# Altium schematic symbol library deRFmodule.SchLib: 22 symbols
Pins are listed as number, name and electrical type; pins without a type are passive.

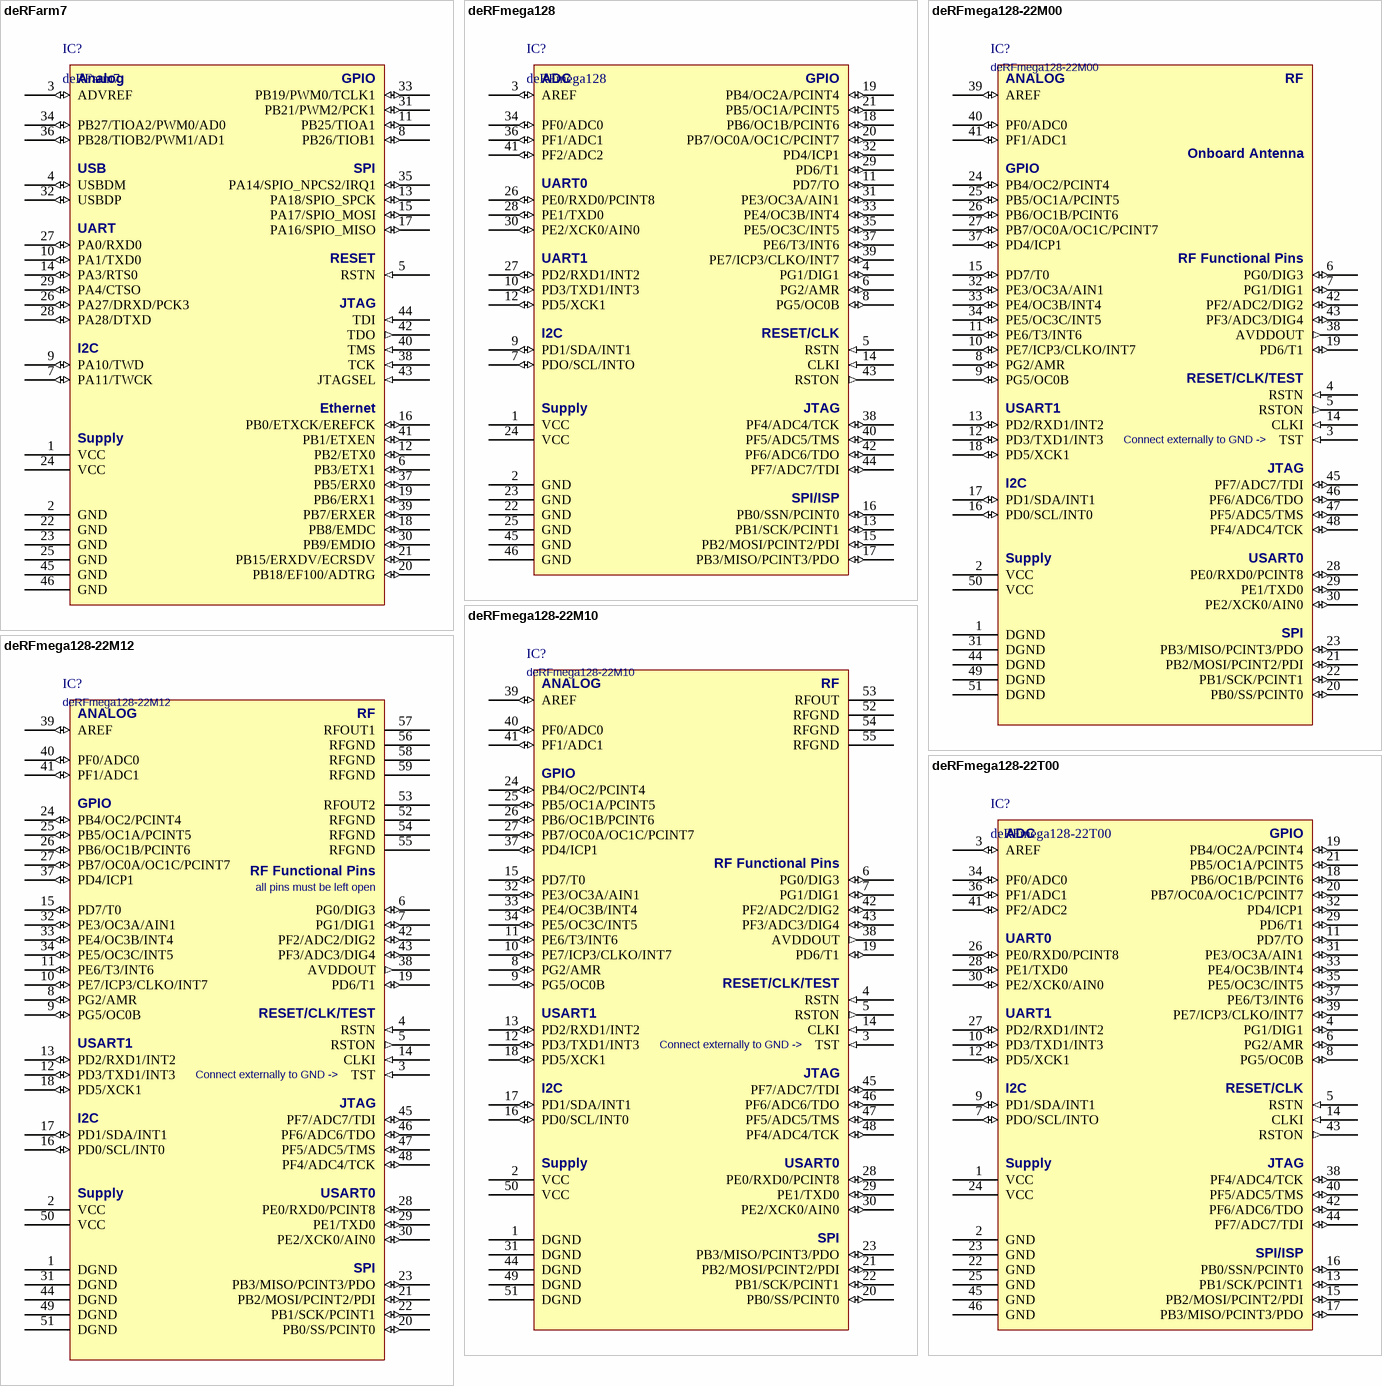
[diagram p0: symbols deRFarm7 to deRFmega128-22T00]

## deRFarm7
designator IC?
IEEE802.15.4 2.4GHz ARM7 based radio module
footprint deRFmodule_THT
footprint deRFmodule_SMT
pins: 1 VCC (power), 2 GND (power), 3 ADVREF (io), 4 USBDM (io), 5 RSTN (in), 6 PB3/ETX1 (io), 7 PA11/TWCK (io), 8 PB26/TIOB1 (io), 9 PA10/TWD (io), 10 PA1/TXD0 (io), 11 PB25/TIOA1 (io), 12 PB2/ETX0 (io), 13 PA18/SPIO_SPCK (io), 14 PA3/RTS0 (io), 15 PA17/SPIO_MOSI (io), 16 PB0/ETXCK/EREFCK (io), 17 PA16/SPIO_MISO (io), 18 PB8/EMDC (io), 19 PB6/ERX1 (io), 20 PB18/EF100/ADTRG (io), 21 PB15/ERXDV/ECRSDV (io), 22 GND (power), 23 GND (power), 24 VCC (power), 25 GND (power), 26 PA27/DRXD/PCK3 (io), 27 PA0/RXD0 (io), 28 PA28/DTXD (io), 29 PA4/CTSO (io), 30 PB9/EMDIO (io), 31 PB21/PWM2/PCK1 (io), 32 USBDP (io), 33 PB19/PWM0/TCLK1 (io), 34 PB27/TIOA2/PWM0/AD0 (io), 35 PA14/SPIO_NPCS2/IRQ1 (io), 36 PB28/TIOB2/PWM1/AD1 (io), 37 PB5/ERX0 (io), 38 TCK (in), 39 PB7/ERXER (io), 40 TMS (in), 41 PB1/ETXEN (io), 42 TDO (out), 43 JTAGSEL (in), 44 TDI (in), 45 GND (power), 46 GND (power)

## deRFmega128
designator IC?
IEEE802.15.4 2.4GHz AVR based radio module
footprint deRFmodule_THT
footprint deRFmodule_SMT
pins: 1 VCC (power), 2 GND (power), 3 AREF (io), 4 PG1/DIG1 (io), 5 RSTN (in), 6 PG2/AMR (io), 7 PDO/SCL/INTO (io), 8 PG5/OC0B (io), 9 PD1/SDA/INT1 (io), 10 PD3/TXD1/INT3 (io), 11 PD7/TO (io), 12 PD5/XCK1 (io), 13 PB1/SCK/PCINT1 (io), 14 CLKI (in), 15 PB2/MOSI/PCINT2/PDI (io), 16 PB0/SSN/PCINT0 (io), 17 PB3/MISO/PCINT3/PDO (io), 18 PB6/OC1B/PCINT6 (io), 19 PB4/OC2A/PCINT4 (io), 20 PB7/OC0A/OC1C/PCINT7 (io), 21 PB5/OC1A/PCINT5 (io), 22 GND (power), 23 GND (power), 24 VCC (power), 25 GND (power), 26 PE0/RXD0/PCINT8 (io), 27 PD2/RXD1/INT2 (io), 28 PE1/TXD0 (io), 29 PD6/T1 (io), 30 PE2/XCK0/AIN0 (io), 31 PE3/OC3A/AIN1 (io), 32 PD4/ICP1 (io), 33 PE4/OC3B/INT4 (io), 34 PF0/ADC0 (io), 35 PE5/OC3C/INT5 (io), 36 PF1/ADC1 (io), 37 PE6/T3/INT6 (io), 38 PF4/ADC4/TCK (io), 39 PE7/ICP3/CLKO/INT7 (io), 40 PF5/ADC5/TMS (io), 41 PF2/ADC2 (io), 42 PF6/ADC6/TDO (io), 43 RSTON (out), 44 PF7/ADC7/TDI (io), 45 GND (power), 46 GND (power)

## deRFmega128-22M00
designator IC?
IEEE802.15.4 2.4GHz AVR based radio module
footprint A-M00 (Footprint deRFmega128-22M00)
pins: 1 DGND (power), 2 VCC (power), 3 TST (in), 4 RSTN (in), 5 RSTON (out), 6 PG0/DIG3 (io), 7 PG1/DIG1 (io), 8 PG2/AMR (io), 9 PG5/OC0B (io), 10 PE7/ICP3/CLKO/INT7 (io), 11 PE6/T3/INT6 (io), 12 PD3/TXD1/INT3 (io), 13 PD2/RXD1/INT2 (io), 14 CLKI (in), 15 PD7/T0 (io), 16 PD0/SCL/INT0 (io), 17 PD1/SDA/INT1 (io), 18 PD5/XCK1 (io), 19 PD6/T1 (io), 20 PB0/SS/PCINT0 (io), 21 PB2/MOSI/PCINT2/PDI (io), 22 PB1/SCK/PCINT1 (io), 23 PB3/MISO/PCINT3/PDO (io), 24 PB4/OC2/PCINT4 (io), 25 PB5/OC1A/PCINT5 (io), 26 PB6/OC1B/PCINT6 (io), 27 PB7/OC0A/OC1C/PCINT7 (io), 28 PE0/RXD0/PCINT8 (io), 29 PE1/TXD0 (io), 30 PE2/XCK0/AIN0 (io), 31 DGND (power), 32 PE3/OC3A/AIN1 (io), 33 PE4/OC3B/INT4 (io), 34 PE5/OC3C/INT5 (io), 35 NC hidden, 36 NC hidden, 37 PD4/ICP1 (io), 38 AVDDOUT (out), 39 AREF (io), 40 PF0/ADC0 (io), 41 PF1/ADC1 (io), 42 PF2/ADC2/DIG2 (io), 43 PF3/ADC3/DIG4 (io), 44 DGND (power), 45 PF7/ADC7/TDI (io), 46 PF6/ADC6/TDO (io), 47 PF5/ADC5/TMS (io), 48 PF4/ADC4/TCK (io), 49 DGND (power), 50 VCC (power), 51 DGND (power)

## deRFmega128-22M10
designator IC?
IEEE802.15.4 2.4GHz AVR based radio module
footprint A-M10 (Footprint deRFmega128-22M10)
pins: 1 DGND (power), 2 VCC (power), 3 TST (in), 4 RSTN (in), 5 RSTON (out), 6 PG0/DIG3 (io), 7 PG1/DIG1 (io), 8 PG2/AMR (io), 9 PG5/OC0B (io), 10 PE7/ICP3/CLKO/INT7 (io), 11 PE6/T3/INT6 (io), 12 PD3/TXD1/INT3 (io), 13 PD2/RXD1/INT2 (io), 14 CLKI (in), 15 PD7/T0 (io), 16 PD0/SCL/INT0 (io), 17 PD1/SDA/INT1 (io), 18 PD5/XCK1 (io), 19 PD6/T1 (io), 20 PB0/SS/PCINT0 (io), 21 PB2/MOSI/PCINT2/PDI (io), 22 PB1/SCK/PCINT1 (io), 23 PB3/MISO/PCINT3/PDO (io), 24 PB4/OC2/PCINT4 (io), 25 PB5/OC1A/PCINT5 (io), 26 PB6/OC1B/PCINT6 (io), 27 PB7/OC0A/OC1C/PCINT7 (io), 28 PE0/RXD0/PCINT8 (io), 29 PE1/TXD0 (io), 30 PE2/XCK0/AIN0 (io), 31 DGND (power), 32 PE3/OC3A/AIN1 (io), 33 PE4/OC3B/INT4 (io), 34 PE5/OC3C/INT5 (io), 35 NC hidden, 36 NC hidden, 37 PD4/ICP1 (io), 38 AVDDOUT (out), 39 AREF (io), 40 PF0/ADC0 (io), 41 PF1/ADC1 (io), 42 PF2/ADC2/DIG2 (io), 43 PF3/ADC3/DIG4 (io), 44 DGND (power), 45 PF7/ADC7/TDI (io), 46 PF6/ADC6/TDO (io), 47 PF5/ADC5/TMS (io), 48 PF4/ADC4/TCK (io), 49 DGND (power), 50 VCC (power), 51 DGND (power), 52 RFGND (power), 53 RFOUT, 54 RFGND (power), 55 RFGND (power)

## deRFmega128-22M12
designator IC?
IEEE802.15.4 2.4GHz AVR based radio module + PA + Ant. Diversity
footprint A-M12 (Footprint deRFmega128-22M12)
pins: 1 DGND (power), 2 VCC (power), 3 TST (in), 4 RSTN (in), 5 RSTON (out), 6 PG0/DIG3 (io), 7 PG1/DIG1 (io), 8 PG2/AMR (io), 9 PG5/OC0B (io), 10 PE7/ICP3/CLKO/INT7 (io), 11 PE6/T3/INT6 (io), 12 PD3/TXD1/INT3 (io), 13 PD2/RXD1/INT2 (io), 14 CLKI (in), 15 PD7/T0 (io), 16 PD0/SCL/INT0 (io), 17 PD1/SDA/INT1 (io), 18 PD5/XCK1 (io), 19 PD6/T1 (io), 20 PB0/SS/PCINT0 (io), 21 PB2/MOSI/PCINT2/PDI (io), 22 PB1/SCK/PCINT1 (io), 23 PB3/MISO/PCINT3/PDO (io), 24 PB4/OC2/PCINT4 (io), 25 PB5/OC1A/PCINT5 (io), 26 PB6/OC1B/PCINT6 (io), 27 PB7/OC0A/OC1C/PCINT7 (io), 28 PE0/RXD0/PCINT8 (io), 29 PE1/TXD0 (io), 30 PE2/XCK0/AIN0 (io), 31 DGND (power), 32 PE3/OC3A/AIN1 (io), 33 PE4/OC3B/INT4 (io), 34 PE5/OC3C/INT5 (io), 35 NC hidden, 36 NC hidden, 37 PD4/ICP1 (io), 38 AVDDOUT (out), 39 AREF (io), 40 PF0/ADC0 (io), 41 PF1/ADC1 (io), 42 PF2/ADC2/DIG2 (io), 43 PF3/ADC3/DIG4 (io), 44 DGND (power), 45 PF7/ADC7/TDI (io), 46 PF6/ADC6/TDO (io), 47 PF5/ADC5/TMS (io), 48 PF4/ADC4/TCK (io), 49 DGND (power), 50 VCC (power), 51 DGND (power), 52 RFGND (power), 53 RFOUT2, 54 RFGND (power), 55 RFGND (power), 56 RFGND (power), 57 RFOUT1, 58 RFGND (power), 59 RFGND (power)

## deRFmega128-22T00
designator IC?
IEEE802.15.4 2.4GHz AVR based radio module
footprint deRFmodule_THT
pins: 1 VCC (power), 2 GND (power), 3 AREF (io), 4 PG1/DIG1 (io), 5 RSTN (in), 6 PG2/AMR (io), 7 PDO/SCL/INTO (io), 8 PG5/OC0B (io), 9 PD1/SDA/INT1 (io), 10 PD3/TXD1/INT3 (io), 11 PD7/TO (io), 12 PD5/XCK1 (io), 13 PB1/SCK/PCINT1 (io), 14 CLKI (in), 15 PB2/MOSI/PCINT2/PDI (io), 16 PB0/SSN/PCINT0 (io), 17 PB3/MISO/PCINT3/PDO (io), 18 PB6/OC1B/PCINT6 (io), 19 PB4/OC2A/PCINT4 (io), 20 PB7/OC0A/OC1C/PCINT7 (io), 21 PB5/OC1A/PCINT5 (io), 22 GND (power), 23 GND (power), 24 VCC (power), 25 GND (power), 26 PE0/RXD0/PCINT8 (io), 27 PD2/RXD1/INT2 (io), 28 PE1/TXD0 (io), 29 PD6/T1 (io), 30 PE2/XCK0/AIN0 (io), 31 PE3/OC3A/AIN1 (io), 32 PD4/ICP1 (io), 33 PE4/OC3B/INT4 (io), 34 PF0/ADC0 (io), 35 PE5/OC3C/INT5 (io), 36 PF1/ADC1 (io), 37 PE6/T3/INT6 (io), 38 PF4/ADC4/TCK (io), 39 PE7/ICP3/CLKO/INT7 (io), 40 PF5/ADC5/TMS (io), 41 PF2/ADC2 (io), 42 PF6/ADC6/TDO (io), 43 RSTON (out), 44 PF7/ADC7/TDI (io), 45 GND (power), 46 GND (power)

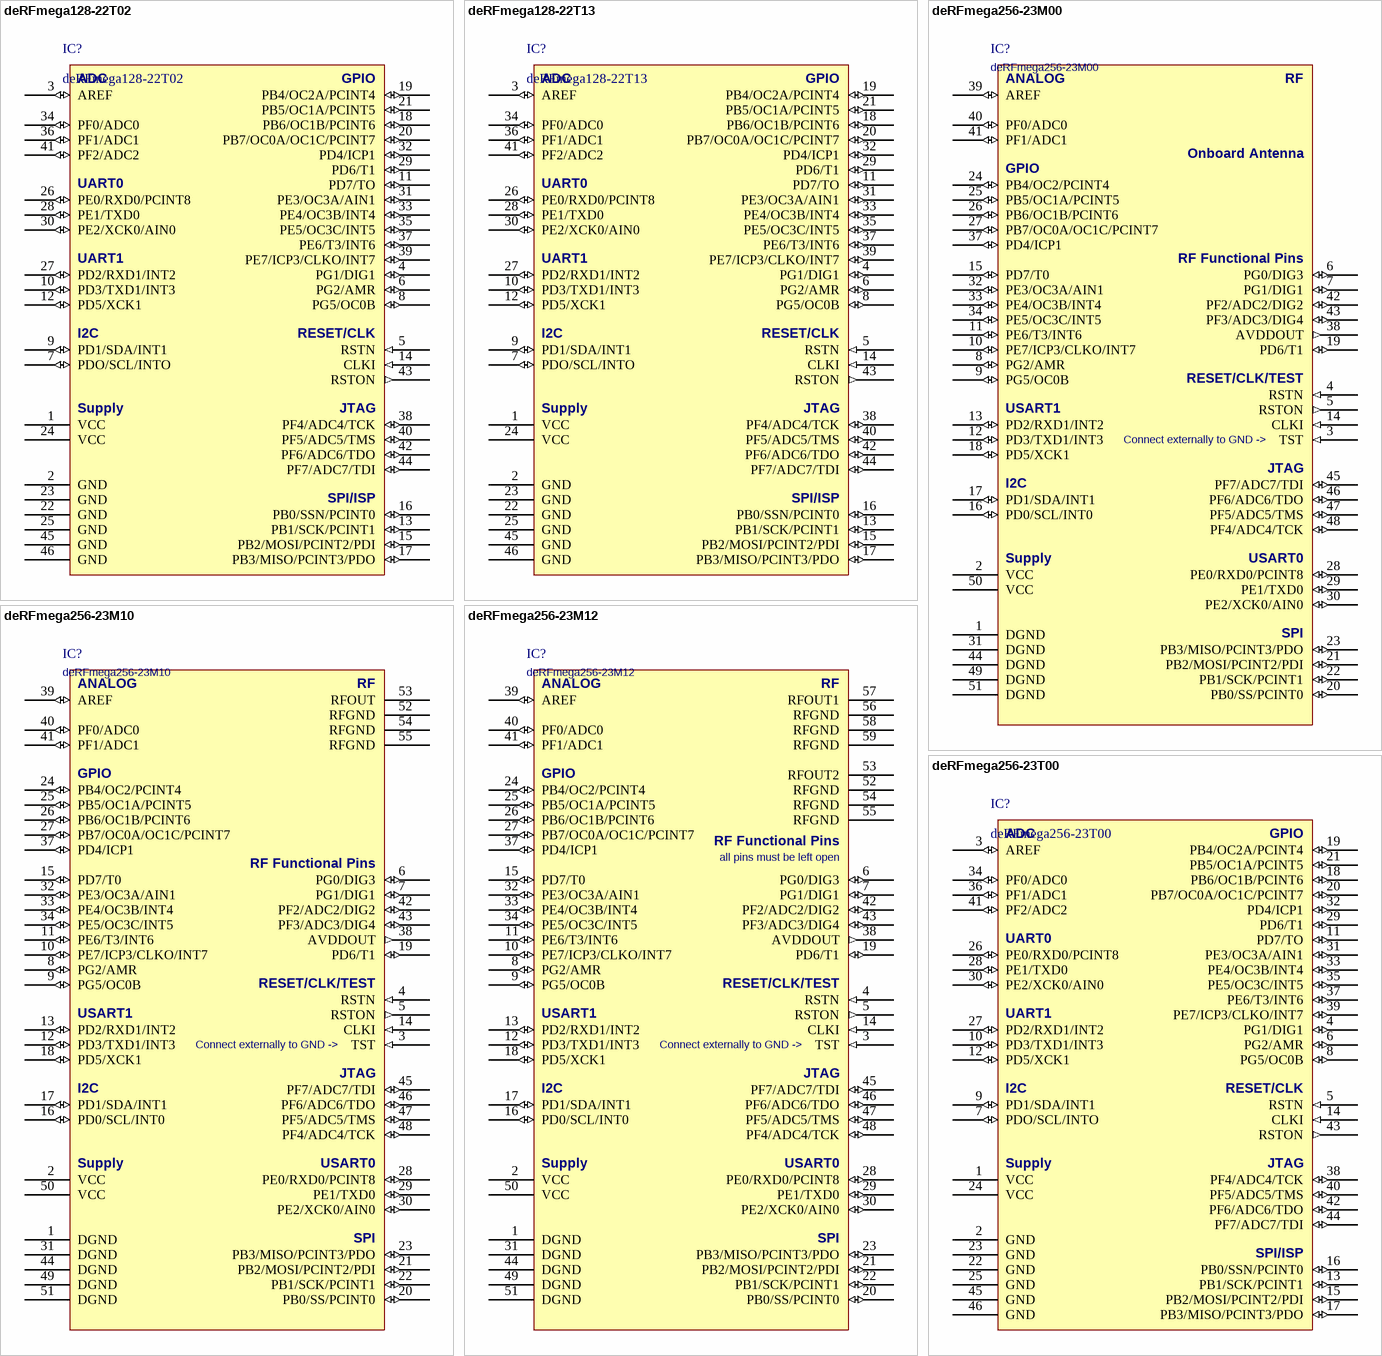
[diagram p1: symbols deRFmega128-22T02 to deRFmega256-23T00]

## deRFmega128-22T02
designator IC?
IEEE802.15.4 2.4GHz AVR based radio module
footprint deRFmodule_THT
pins: 1 VCC (power), 2 GND (power), 3 AREF (io), 4 PG1/DIG1 (io), 5 RSTN (in), 6 PG2/AMR (io), 7 PDO/SCL/INTO (io), 8 PG5/OC0B (io), 9 PD1/SDA/INT1 (io), 10 PD3/TXD1/INT3 (io), 11 PD7/TO (io), 12 PD5/XCK1 (io), 13 PB1/SCK/PCINT1 (io), 14 CLKI (in), 15 PB2/MOSI/PCINT2/PDI (io), 16 PB0/SSN/PCINT0 (io), 17 PB3/MISO/PCINT3/PDO (io), 18 PB6/OC1B/PCINT6 (io), 19 PB4/OC2A/PCINT4 (io), 20 PB7/OC0A/OC1C/PCINT7 (io), 21 PB5/OC1A/PCINT5 (io), 22 GND (power), 23 GND (power), 24 VCC (power), 25 GND (power), 26 PE0/RXD0/PCINT8 (io), 27 PD2/RXD1/INT2 (io), 28 PE1/TXD0 (io), 29 PD6/T1 (io), 30 PE2/XCK0/AIN0 (io), 31 PE3/OC3A/AIN1 (io), 32 PD4/ICP1 (io), 33 PE4/OC3B/INT4 (io), 34 PF0/ADC0 (io), 35 PE5/OC3C/INT5 (io), 36 PF1/ADC1 (io), 37 PE6/T3/INT6 (io), 38 PF4/ADC4/TCK (io), 39 PE7/ICP3/CLKO/INT7 (io), 40 PF5/ADC5/TMS (io), 41 PF2/ADC2 (io), 42 PF6/ADC6/TDO (io), 43 RSTON (out), 44 PF7/ADC7/TDI (io), 45 GND (power), 46 GND (power)

## deRFmega128-22T13
designator IC?
IEEE802.15.4 2.4GHz AVR based radio module
footprint deRFmodule_THT
pins: 1 VCC (power), 2 GND (power), 3 AREF (io), 4 PG1/DIG1 (io), 5 RSTN (in), 6 PG2/AMR (io), 7 PDO/SCL/INTO (io), 8 PG5/OC0B (io), 9 PD1/SDA/INT1 (io), 10 PD3/TXD1/INT3 (io), 11 PD7/TO (io), 12 PD5/XCK1 (io), 13 PB1/SCK/PCINT1 (io), 14 CLKI (in), 15 PB2/MOSI/PCINT2/PDI (io), 16 PB0/SSN/PCINT0 (io), 17 PB3/MISO/PCINT3/PDO (io), 18 PB6/OC1B/PCINT6 (io), 19 PB4/OC2A/PCINT4 (io), 20 PB7/OC0A/OC1C/PCINT7 (io), 21 PB5/OC1A/PCINT5 (io), 22 GND (power), 23 GND (power), 24 VCC (power), 25 GND (power), 26 PE0/RXD0/PCINT8 (io), 27 PD2/RXD1/INT2 (io), 28 PE1/TXD0 (io), 29 PD6/T1 (io), 30 PE2/XCK0/AIN0 (io), 31 PE3/OC3A/AIN1 (io), 32 PD4/ICP1 (io), 33 PE4/OC3B/INT4 (io), 34 PF0/ADC0 (io), 35 PE5/OC3C/INT5 (io), 36 PF1/ADC1 (io), 37 PE6/T3/INT6 (io), 38 PF4/ADC4/TCK (io), 39 PE7/ICP3/CLKO/INT7 (io), 40 PF5/ADC5/TMS (io), 41 PF2/ADC2 (io), 42 PF6/ADC6/TDO (io), 43 RSTON (out), 44 PF7/ADC7/TDI (io), 45 GND (power), 46 GND (power)

## deRFmega256-23M00
designator IC?
IEEE802.15.4 2.4GHz AVR based radio module
footprint A-M00 (Footprint deRFmega128-22M00)
pins: 1 DGND (power), 2 VCC (power), 3 TST (in), 4 RSTN (in), 5 RSTON (out), 6 PG0/DIG3 (io), 7 PG1/DIG1 (io), 8 PG2/AMR (io), 9 PG5/OC0B (io), 10 PE7/ICP3/CLKO/INT7 (io), 11 PE6/T3/INT6 (io), 12 PD3/TXD1/INT3 (io), 13 PD2/RXD1/INT2 (io), 14 CLKI (in), 15 PD7/T0 (io), 16 PD0/SCL/INT0 (io), 17 PD1/SDA/INT1 (io), 18 PD5/XCK1 (io), 19 PD6/T1 (io), 20 PB0/SS/PCINT0 (io), 21 PB2/MOSI/PCINT2/PDI (io), 22 PB1/SCK/PCINT1 (io), 23 PB3/MISO/PCINT3/PDO (io), 24 PB4/OC2/PCINT4 (io), 25 PB5/OC1A/PCINT5 (io), 26 PB6/OC1B/PCINT6 (io), 27 PB7/OC0A/OC1C/PCINT7 (io), 28 PE0/RXD0/PCINT8 (io), 29 PE1/TXD0 (io), 30 PE2/XCK0/AIN0 (io), 31 DGND (power), 32 PE3/OC3A/AIN1 (io), 33 PE4/OC3B/INT4 (io), 34 PE5/OC3C/INT5 (io), 35 NC hidden, 36 NC hidden, 37 PD4/ICP1 (io), 38 AVDDOUT (out), 39 AREF (io), 40 PF0/ADC0 (io), 41 PF1/ADC1 (io), 42 PF2/ADC2/DIG2 (io), 43 PF3/ADC3/DIG4 (io), 44 DGND (power), 45 PF7/ADC7/TDI (io), 46 PF6/ADC6/TDO (io), 47 PF5/ADC5/TMS (io), 48 PF4/ADC4/TCK (io), 49 DGND (power), 50 VCC (power), 51 DGND (power)

## deRFmega256-23M10
designator IC?
IEEE802.15.4 2.4GHz AVR based radio module
footprint A-M10 (Footprint deRFmega128-22M10)
pins: 1 DGND (power), 2 VCC (power), 3 TST (in), 4 RSTN (in), 5 RSTON (out), 6 PG0/DIG3 (io), 7 PG1/DIG1 (io), 8 PG2/AMR (io), 9 PG5/OC0B (io), 10 PE7/ICP3/CLKO/INT7 (io), 11 PE6/T3/INT6 (io), 12 PD3/TXD1/INT3 (io), 13 PD2/RXD1/INT2 (io), 14 CLKI (in), 15 PD7/T0 (io), 16 PD0/SCL/INT0 (io), 17 PD1/SDA/INT1 (io), 18 PD5/XCK1 (io), 19 PD6/T1 (io), 20 PB0/SS/PCINT0 (io), 21 PB2/MOSI/PCINT2/PDI (io), 22 PB1/SCK/PCINT1 (io), 23 PB3/MISO/PCINT3/PDO (io), 24 PB4/OC2/PCINT4 (io), 25 PB5/OC1A/PCINT5 (io), 26 PB6/OC1B/PCINT6 (io), 27 PB7/OC0A/OC1C/PCINT7 (io), 28 PE0/RXD0/PCINT8 (io), 29 PE1/TXD0 (io), 30 PE2/XCK0/AIN0 (io), 31 DGND (power), 32 PE3/OC3A/AIN1 (io), 33 PE4/OC3B/INT4 (io), 34 PE5/OC3C/INT5 (io), 35 NC hidden, 36 NC hidden, 37 PD4/ICP1 (io), 38 AVDDOUT (out), 39 AREF (io), 40 PF0/ADC0 (io), 41 PF1/ADC1 (io), 42 PF2/ADC2/DIG2 (io), 43 PF3/ADC3/DIG4 (io), 44 DGND (power), 45 PF7/ADC7/TDI (io), 46 PF6/ADC6/TDO (io), 47 PF5/ADC5/TMS (io), 48 PF4/ADC4/TCK (io), 49 DGND (power), 50 VCC (power), 51 DGND (power), 52 RFGND (power), 53 RFOUT, 54 RFGND (power), 55 RFGND (power)

## deRFmega256-23M12
designator IC?
IEEE802.15.4 2.4GHz AVR based radio module + PA + Ant. Diversity
footprint A-M12 (Footprint deRFmega128-22M12)
pins: 1 DGND (power), 2 VCC (power), 3 TST (in), 4 RSTN (in), 5 RSTON (out), 6 PG0/DIG3 (io), 7 PG1/DIG1 (io), 8 PG2/AMR (io), 9 PG5/OC0B (io), 10 PE7/ICP3/CLKO/INT7 (io), 11 PE6/T3/INT6 (io), 12 PD3/TXD1/INT3 (io), 13 PD2/RXD1/INT2 (io), 14 CLKI (in), 15 PD7/T0 (io), 16 PD0/SCL/INT0 (io), 17 PD1/SDA/INT1 (io), 18 PD5/XCK1 (io), 19 PD6/T1 (io), 20 PB0/SS/PCINT0 (io), 21 PB2/MOSI/PCINT2/PDI (io), 22 PB1/SCK/PCINT1 (io), 23 PB3/MISO/PCINT3/PDO (io), 24 PB4/OC2/PCINT4 (io), 25 PB5/OC1A/PCINT5 (io), 26 PB6/OC1B/PCINT6 (io), 27 PB7/OC0A/OC1C/PCINT7 (io), 28 PE0/RXD0/PCINT8 (io), 29 PE1/TXD0 (io), 30 PE2/XCK0/AIN0 (io), 31 DGND (power), 32 PE3/OC3A/AIN1 (io), 33 PE4/OC3B/INT4 (io), 34 PE5/OC3C/INT5 (io), 35 NC hidden, 36 NC hidden, 37 PD4/ICP1 (io), 38 AVDDOUT (out), 39 AREF (io), 40 PF0/ADC0 (io), 41 PF1/ADC1 (io), 42 PF2/ADC2/DIG2 (io), 43 PF3/ADC3/DIG4 (io), 44 DGND (power), 45 PF7/ADC7/TDI (io), 46 PF6/ADC6/TDO (io), 47 PF5/ADC5/TMS (io), 48 PF4/ADC4/TCK (io), 49 DGND (power), 50 VCC (power), 51 DGND (power), 52 RFGND (power), 53 RFOUT2, 54 RFGND (power), 55 RFGND (power), 56 RFGND (power), 57 RFOUT1, 58 RFGND (power), 59 RFGND (power)

## deRFmega256-23T00
designator IC?
IEEE802.15.4 2.4GHz AVR based radio module
footprint deRFmodule_THT
pins: 1 VCC (power), 2 GND (power), 3 AREF (io), 4 PG1/DIG1 (io), 5 RSTN (in), 6 PG2/AMR (io), 7 PDO/SCL/INTO (io), 8 PG5/OC0B (io), 9 PD1/SDA/INT1 (io), 10 PD3/TXD1/INT3 (io), 11 PD7/TO (io), 12 PD5/XCK1 (io), 13 PB1/SCK/PCINT1 (io), 14 CLKI (in), 15 PB2/MOSI/PCINT2/PDI (io), 16 PB0/SSN/PCINT0 (io), 17 PB3/MISO/PCINT3/PDO (io), 18 PB6/OC1B/PCINT6 (io), 19 PB4/OC2A/PCINT4 (io), 20 PB7/OC0A/OC1C/PCINT7 (io), 21 PB5/OC1A/PCINT5 (io), 22 GND (power), 23 GND (power), 24 VCC (power), 25 GND (power), 26 PE0/RXD0/PCINT8 (io), 27 PD2/RXD1/INT2 (io), 28 PE1/TXD0 (io), 29 PD6/T1 (io), 30 PE2/XCK0/AIN0 (io), 31 PE3/OC3A/AIN1 (io), 32 PD4/ICP1 (io), 33 PE4/OC3B/INT4 (io), 34 PF0/ADC0 (io), 35 PE5/OC3C/INT5 (io), 36 PF1/ADC1 (io), 37 PE6/T3/INT6 (io), 38 PF4/ADC4/TCK (io), 39 PE7/ICP3/CLKO/INT7 (io), 40 PF5/ADC5/TMS (io), 41 PF2/ADC2 (io), 42 PF6/ADC6/TDO (io), 43 RSTON (out), 44 PF7/ADC7/TDI (io), 45 GND (power), 46 GND (power)

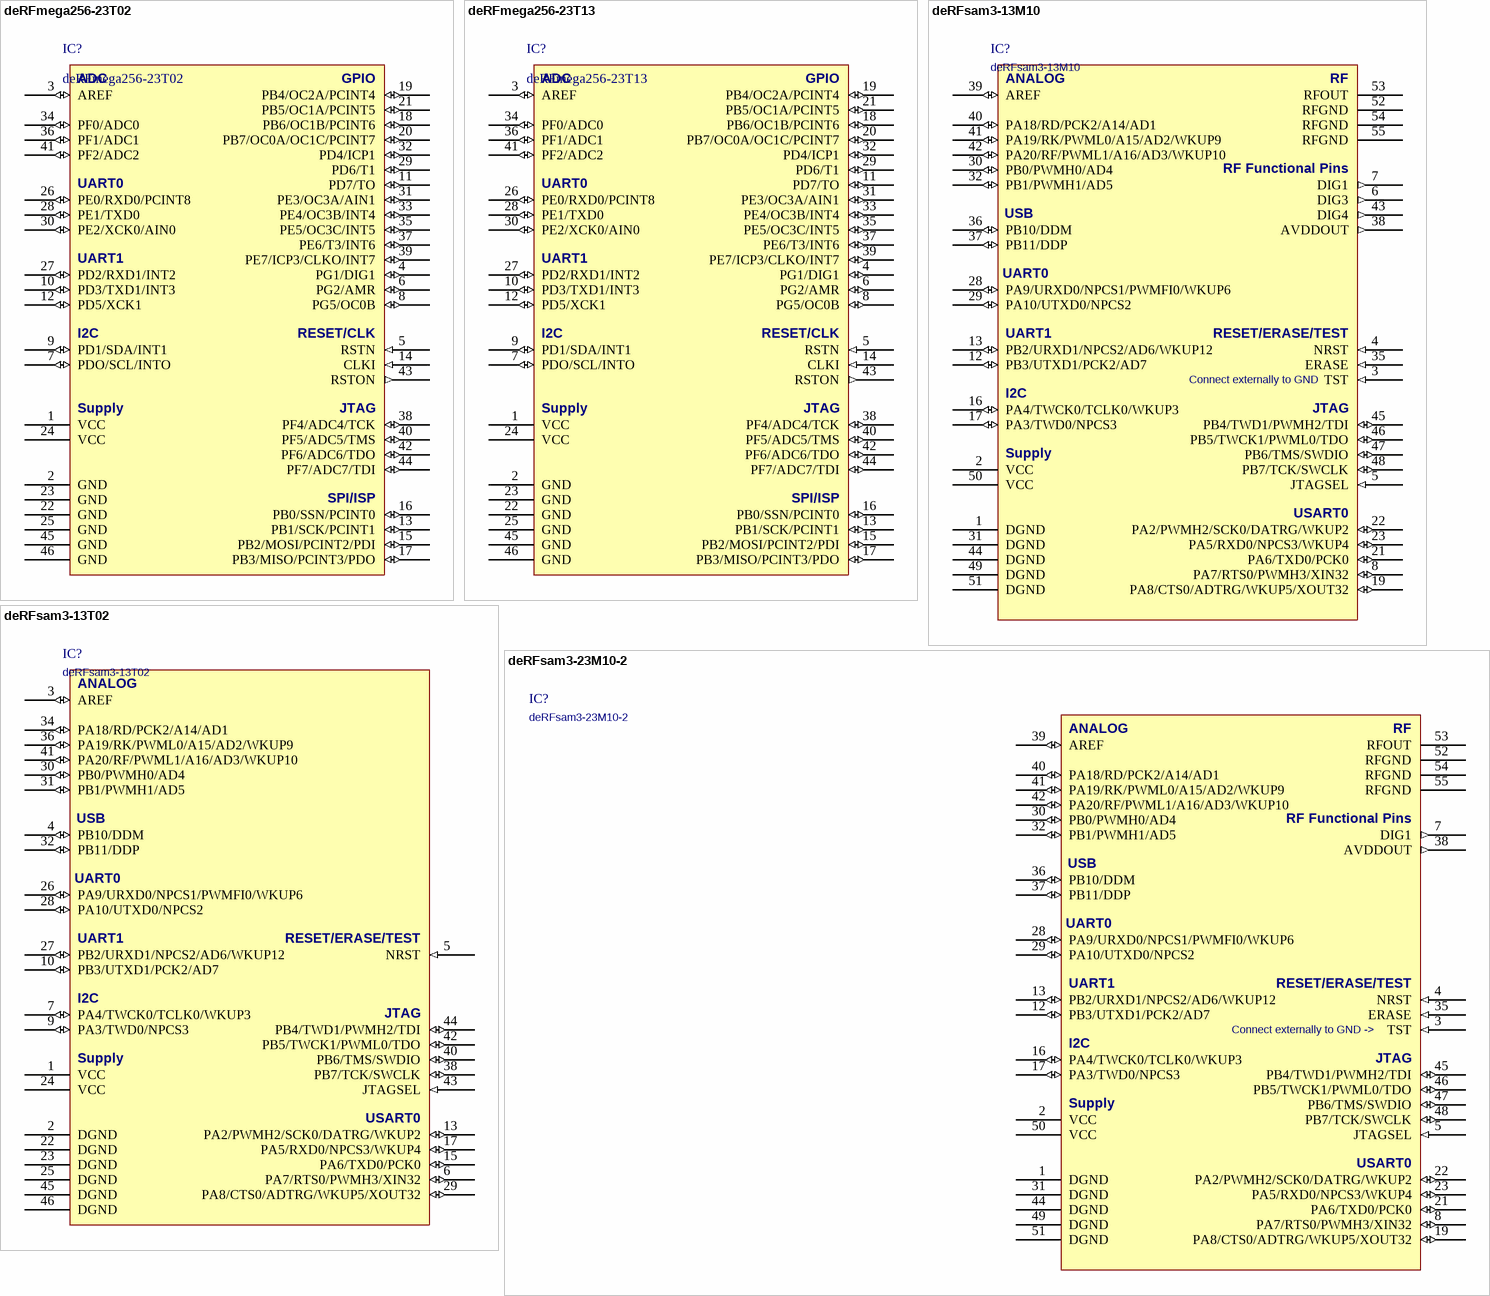
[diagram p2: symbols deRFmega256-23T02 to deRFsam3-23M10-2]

## deRFmega256-23T02
designator IC?
IEEE802.15.4 2.4GHz AVR based radio module
footprint deRFmodule_THT
pins: 1 VCC (power), 2 GND (power), 3 AREF (io), 4 PG1/DIG1 (io), 5 RSTN (in), 6 PG2/AMR (io), 7 PDO/SCL/INTO (io), 8 PG5/OC0B (io), 9 PD1/SDA/INT1 (io), 10 PD3/TXD1/INT3 (io), 11 PD7/TO (io), 12 PD5/XCK1 (io), 13 PB1/SCK/PCINT1 (io), 14 CLKI (in), 15 PB2/MOSI/PCINT2/PDI (io), 16 PB0/SSN/PCINT0 (io), 17 PB3/MISO/PCINT3/PDO (io), 18 PB6/OC1B/PCINT6 (io), 19 PB4/OC2A/PCINT4 (io), 20 PB7/OC0A/OC1C/PCINT7 (io), 21 PB5/OC1A/PCINT5 (io), 22 GND (power), 23 GND (power), 24 VCC (power), 25 GND (power), 26 PE0/RXD0/PCINT8 (io), 27 PD2/RXD1/INT2 (io), 28 PE1/TXD0 (io), 29 PD6/T1 (io), 30 PE2/XCK0/AIN0 (io), 31 PE3/OC3A/AIN1 (io), 32 PD4/ICP1 (io), 33 PE4/OC3B/INT4 (io), 34 PF0/ADC0 (io), 35 PE5/OC3C/INT5 (io), 36 PF1/ADC1 (io), 37 PE6/T3/INT6 (io), 38 PF4/ADC4/TCK (io), 39 PE7/ICP3/CLKO/INT7 (io), 40 PF5/ADC5/TMS (io), 41 PF2/ADC2 (io), 42 PF6/ADC6/TDO (io), 43 RSTON (out), 44 PF7/ADC7/TDI (io), 45 GND (power), 46 GND (power)

## deRFmega256-23T13
designator IC?
IEEE802.15.4 2.4GHz AVR based radio module
footprint deRFmodule_THT
pins: 1 VCC (power), 2 GND (power), 3 AREF (io), 4 PG1/DIG1 (io), 5 RSTN (in), 6 PG2/AMR (io), 7 PDO/SCL/INTO (io), 8 PG5/OC0B (io), 9 PD1/SDA/INT1 (io), 10 PD3/TXD1/INT3 (io), 11 PD7/TO (io), 12 PD5/XCK1 (io), 13 PB1/SCK/PCINT1 (io), 14 CLKI (in), 15 PB2/MOSI/PCINT2/PDI (io), 16 PB0/SSN/PCINT0 (io), 17 PB3/MISO/PCINT3/PDO (io), 18 PB6/OC1B/PCINT6 (io), 19 PB4/OC2A/PCINT4 (io), 20 PB7/OC0A/OC1C/PCINT7 (io), 21 PB5/OC1A/PCINT5 (io), 22 GND (power), 23 GND (power), 24 VCC (power), 25 GND (power), 26 PE0/RXD0/PCINT8 (io), 27 PD2/RXD1/INT2 (io), 28 PE1/TXD0 (io), 29 PD6/T1 (io), 30 PE2/XCK0/AIN0 (io), 31 PE3/OC3A/AIN1 (io), 32 PD4/ICP1 (io), 33 PE4/OC3B/INT4 (io), 34 PF0/ADC0 (io), 35 PE5/OC3C/INT5 (io), 36 PF1/ADC1 (io), 37 PE6/T3/INT6 (io), 38 PF4/ADC4/TCK (io), 39 PE7/ICP3/CLKO/INT7 (io), 40 PF5/ADC5/TMS (io), 41 PF2/ADC2 (io), 42 PF6/ADC6/TDO (io), 43 RSTON (out), 44 PF7/ADC7/TDI (io), 45 GND (power), 46 GND (power)

## deRFsam3-13M10
designator IC?
IEEE802.15.4 Sub-GHz Cortex-M3 based radio module
footprint S-M10 (Footprint deRFsam3-xxM10-x)
pins: 1 DGND (power), 2 VCC (power), 3 TST (in), 4 NRST (in), 5 JTAGSEL (in), 6 DIG3 (out), 7 DIG1 (out), 8 PA7/RTS0/PWMH3/XIN32 (io), 9 NC hidden, 10 NC hidden, 11 NC hidden, 12 PB3/UTXD1/PCK2/AD7 (io), 13 PB2/URXD1/NPCS2/AD6/WKUP12 (io), 14 NC hidden, 15 NC hidden, 16 PA4/TWCK0/TCLK0/WKUP3 (io), 17 PA3/TWD0/NPCS3 (io), 18 NC hidden, 19 PA8/CTS0/ADTRG/WKUP5/XOUT32 (io), 20 NC hidden, 21 PA6/TXD0/PCK0 (io), 22 PA2/PWMH2/SCK0/DATRG/WKUP2 (io), 23 PA5/RXD0/NPCS3/WKUP4 (io), 24 NC hidden, 25 NC hidden, 26 NC hidden, 27 NC hidden, 28 PA9/URXD0/NPCS1/PWMFI0/WKUP6 (io), 29 PA10/UTXD0/NPCS2 (io), 30 PB0/PWMH0/AD4 (io), 31 DGND (power), 32 PB1/PWMH1/AD5 (io), 33 NC hidden, 34 NC hidden, 35 ERASE (in), 36 PB10/DDM (io), 37 PB11/DDP (io), 38 AVDDOUT (out), 39 AREF (io), 40 PA18/RD/PCK2/A14/AD1 (io), 41 PA19/RK/PWML0/A15/AD2/WKUP9 (io), 42 PA20/RF/PWML1/A16/AD3/WKUP10 (io), 43 DIG4 (out), 44 DGND (power), 45 PB4/TWD1/PWMH2/TDI (io), 46 PB5/TWCK1/PWML0/TDO (io), 47 PB6/TMS/SWDIO (io), 48 PB7/TCK/SWCLK (io), 49 DGND (power), 50 VCC (power), 51 DGND (power), 52 RFGND (power), 53 RFOUT, 54 RFGND (power), 55 RFGND (power)

## deRFsam3-13T02
designator IC?
IEEE802.15.4 Sub-GHz Cortex-M3 based radio module
footprint deRFmodule_THT
pins: 1 VCC (power), 2 DGND (power), 3 AREF (io), 4 PB10/DDM (io), 5 NRST (in), 6 PA7/RTS0/PWMH3/XIN32 (io), 7 PA4/TWCK0/TCLK0/WKUP3 (io), 8 NC hidden, 9 PA3/TWD0/NPCS3 (io), 10 PB3/UTXD1/PCK2/AD7 (io), 11 NC hidden, 12 NC hidden, 13 PA2/PWMH2/SCK0/DATRG/WKUP2 (io), 14 NC hidden, 15 PA6/TXD0/PCK0 (io), 16 NC hidden, 17 PA5/RXD0/NPCS3/WKUP4 (io), 18 NC hidden, 19 NC hidden, 20 NC hidden, 21 NC hidden, 22 DGND (power), 23 DGND (power), 24 VCC (power), 25 DGND (power), 26 PA9/URXD0/NPCS1/PWMFI0/WKUP6 (io), 27 PB2/URXD1/NPCS2/AD6/WKUP12 (io), 28 PA10/UTXD0/NPCS2 (io), 29 PA8/CTS0/ADTRG/WKUP5/XOUT32 (io), 30 PB0/PWMH0/AD4 (io), 31 PB1/PWMH1/AD5 (io), 32 PB11/DDP (io), 33 NC hidden, 34 PA18/RD/PCK2/A14/AD1 (io), 35 NC hidden, 36 PA19/RK/PWML0/A15/AD2/WKUP9 (io), 37 NC hidden, 38 PB7/TCK/SWCLK (io), 39 NC hidden, 40 PB6/TMS/SWDIO (io), 41 PA20/RF/PWML1/A16/AD3/WKUP10 (io), 42 PB5/TWCK1/PWML0/TDO (io), 43 JTAGSEL (in), 44 PB4/TWD1/PWMH2/TDI (io), 45 DGND (power), 46 DGND (power)

## deRFsam3-23M10-2
designator IC?
IEEE802.15.4 2.4GHz Cortex-M3 based radio module
footprint S-M10 (Footprint deRFsam3-xxM10-x)
pins: 1 DGND (power), 2 VCC (power), 3 TST (in), 4 NRST (in), 5 JTAGSEL (in), 6 NC hidden, 7 DIG1 (out), 8 PA7/RTS0/PWMH3/XIN32 (io), 9 NC hidden, 10 NC hidden, 11 NC hidden, 12 PB3/UTXD1/PCK2/AD7 (io), 13 PB2/URXD1/NPCS2/AD6/WKUP12 (io), 14 NC hidden, 15 NC hidden, 16 PA4/TWCK0/TCLK0/WKUP3 (io), 17 PA3/TWD0/NPCS3 (io), 18 NC hidden, 19 PA8/CTS0/ADTRG/WKUP5/XOUT32 (io), 20 NC hidden, 21 PA6/TXD0/PCK0 (io), 22 PA2/PWMH2/SCK0/DATRG/WKUP2 (io), 23 PA5/RXD0/NPCS3/WKUP4 (io), 24 NC hidden, 25 NC hidden, 26 NC hidden, 27 NC hidden, 28 PA9/URXD0/NPCS1/PWMFI0/WKUP6 (io), 29 PA10/UTXD0/NPCS2 (io), 30 PB0/PWMH0/AD4 (io), 31 DGND (power), 32 PB1/PWMH1/AD5 (io), 33 NC hidden, 34 NC hidden, 35 ERASE (in), 36 PB10/DDM (io), 37 PB11/DDP (io), 38 AVDDOUT (out), 39 AREF (io), 40 PA18/RD/PCK2/A14/AD1 (io), 41 PA19/RK/PWML0/A15/AD2/WKUP9 (io), 42 PA20/RF/PWML1/A16/AD3/WKUP10 (io), 43 NC hidden, 44 DGND (power), 45 PB4/TWD1/PWMH2/TDI (io), 46 PB5/TWCK1/PWML0/TDO (io), 47 PB6/TMS/SWDIO (io), 48 PB7/TCK/SWCLK (io), 49 DGND (power), 50 VCC (power), 51 DGND (power), 52 RFGND (power), 53 RFOUT, 54 RFGND (power), 55 RFGND (power)

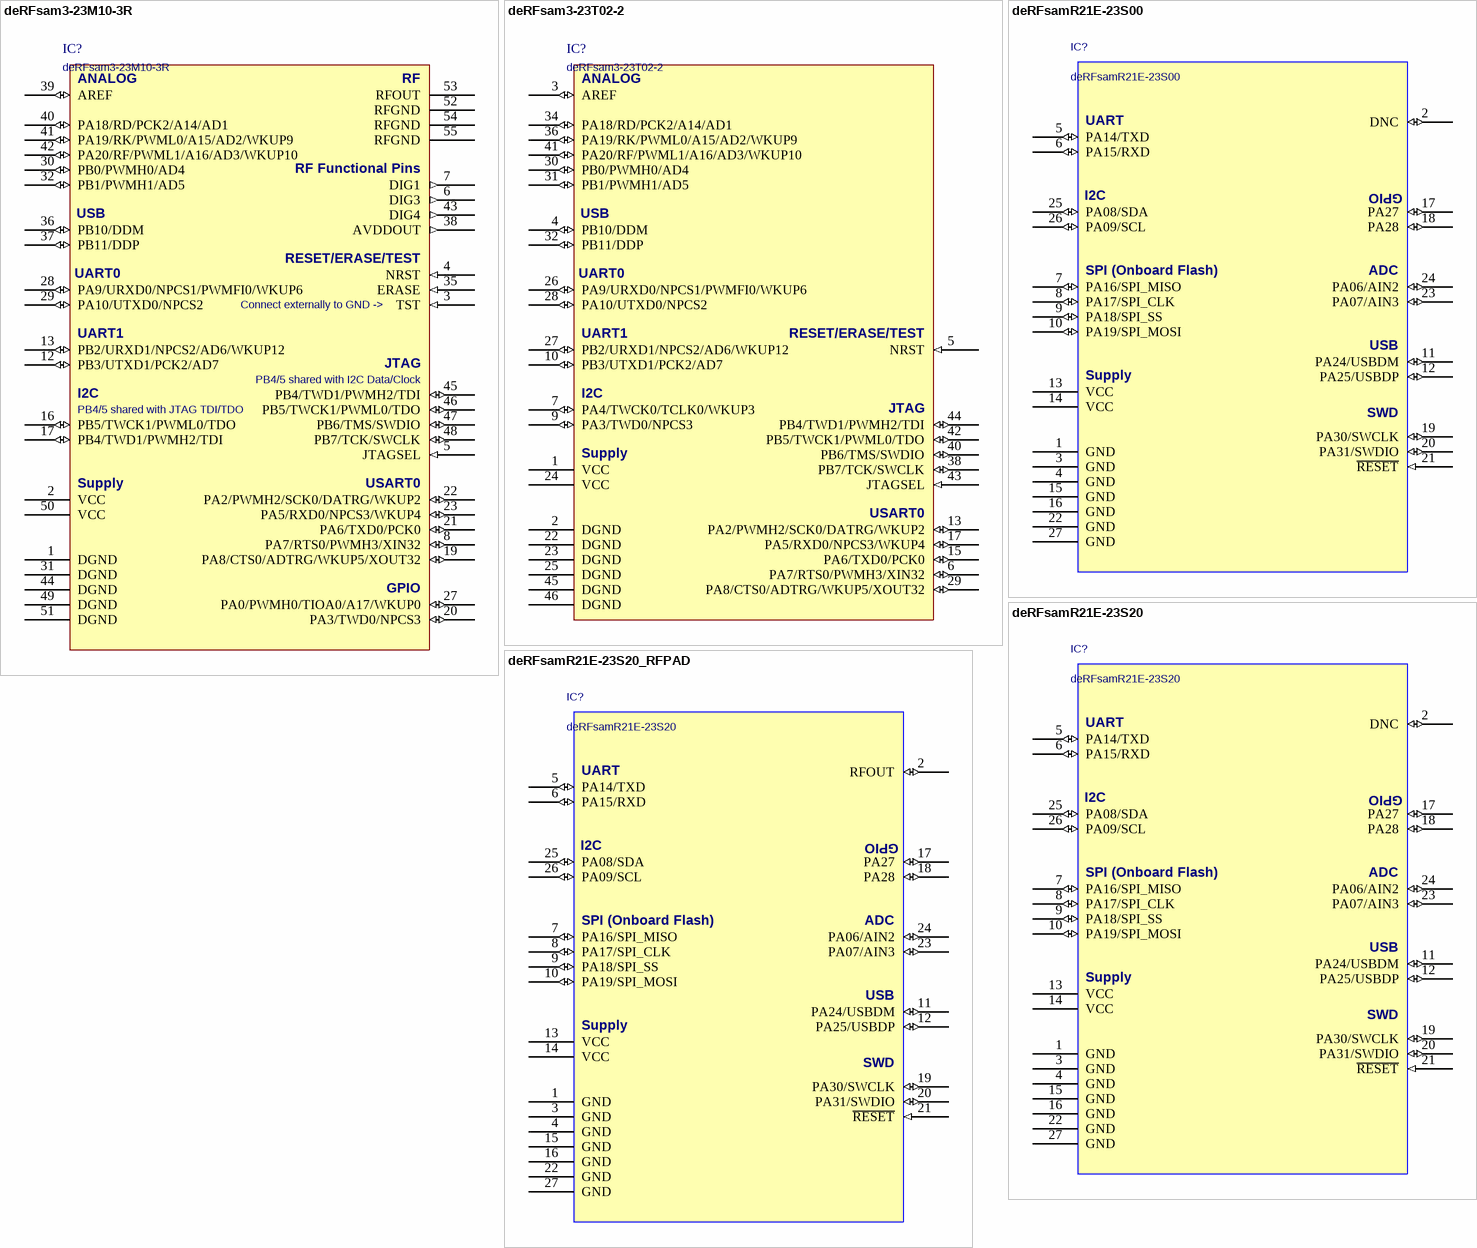
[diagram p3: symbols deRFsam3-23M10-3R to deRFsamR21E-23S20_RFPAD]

## deRFsam3-23M10-3R
designator IC?
IEEE802.15.4 2.4GHz Cortex-M3 based radio module
footprint S-M10 (Footprint deRFsam3-xxM10-x)
pins: 1 DGND (power), 2 VCC (power), 3 TST (in), 4 NRST (in), 5 JTAGSEL (in), 6 DIG3 (out), 7 DIG1 (out), 8 PA7/RTS0/PWMH3/XIN32 (io), 9 NC hidden, 10 NC hidden, 11 NC hidden, 12 PB3/UTXD1/PCK2/AD7 (io), 13 PB2/URXD1/NPCS2/AD6/WKUP12 (io), 14 NC hidden, 15 NC hidden, 16 PB5/TWCK1/PWML0/TDO (io), 17 PB4/TWD1/PWMH2/TDI (io), 18 NC hidden, 19 PA8/CTS0/ADTRG/WKUP5/XOUT32 (io), 20 PA3/TWD0/NPCS3 (io), 21 PA6/TXD0/PCK0 (io), 22 PA2/PWMH2/SCK0/DATRG/WKUP2 (io), 23 PA5/RXD0/NPCS3/WKUP4 (io), 24 NC hidden, 25 NC hidden, 26 NC hidden, 27 PA0/PWMH0/TIOA0/A17/WKUP0 (io), 28 PA9/URXD0/NPCS1/PWMFI0/WKUP6 (io), 29 PA10/UTXD0/NPCS2 (io), 30 PB0/PWMH0/AD4 (io), 31 DGND (power), 32 PB1/PWMH1/AD5 (io), 33 NC hidden, 34 NC hidden, 35 ERASE (in), 36 PB10/DDM (io), 37 PB11/DDP (io), 38 AVDDOUT (out), 39 AREF (io), 40 PA18/RD/PCK2/A14/AD1 (io), 41 PA19/RK/PWML0/A15/AD2/WKUP9 (io), 42 PA20/RF/PWML1/A16/AD3/WKUP10 (io), 43 DIG4 (out), 44 DGND (power), 45 PB4/TWD1/PWMH2/TDI (io), 46 PB5/TWCK1/PWML0/TDO (io), 47 PB6/TMS/SWDIO (io), 48 PB7/TCK/SWCLK (io), 49 DGND (power), 50 VCC (power), 51 DGND (power), 52 RFGND (power), 53 RFOUT, 54 RFGND (power), 55 RFGND (power)

## deRFsam3-23T02-2
designator IC?
IEEE802.15.4 Sub-GHz Cortex-M3 based radio module
footprint deRFmodule_THT
pins: 1 VCC (power), 2 DGND (power), 3 AREF (io), 4 PB10/DDM (io), 5 NRST (in), 6 PA7/RTS0/PWMH3/XIN32 (io), 7 PA4/TWCK0/TCLK0/WKUP3 (io), 8 NC hidden, 9 PA3/TWD0/NPCS3 (io), 10 PB3/UTXD1/PCK2/AD7 (io), 11 NC hidden, 12 NC hidden, 13 PA2/PWMH2/SCK0/DATRG/WKUP2 (io), 14 NC hidden, 15 PA6/TXD0/PCK0 (io), 16 NC hidden, 17 PA5/RXD0/NPCS3/WKUP4 (io), 18 NC hidden, 19 NC hidden, 20 NC hidden, 21 NC hidden, 22 DGND (power), 23 DGND (power), 24 VCC (power), 25 DGND (power), 26 PA9/URXD0/NPCS1/PWMFI0/WKUP6 (io), 27 PB2/URXD1/NPCS2/AD6/WKUP12 (io), 28 PA10/UTXD0/NPCS2 (io), 29 PA8/CTS0/ADTRG/WKUP5/XOUT32 (io), 30 PB0/PWMH0/AD4 (io), 31 PB1/PWMH1/AD5 (io), 32 PB11/DDP (io), 33 NC hidden, 34 PA18/RD/PCK2/A14/AD1 (io), 35 NC hidden, 36 PA19/RK/PWML0/A15/AD2/WKUP9 (io), 37 NC hidden, 38 PB7/TCK/SWCLK (io), 39 NC hidden, 40 PB6/TMS/SWDIO (io), 41 PA20/RF/PWML1/A16/AD3/WKUP10 (io), 42 PB5/TWCK1/PWML0/TDO (io), 43 JTAGSEL (in), 44 PB4/TWD1/PWMH2/TDI (io), 45 DGND (power), 46 DGND (power)

## deRFsamR21E-23S00
designator IC?
IEEE802.15.4 2.4GHz Cortex-M0 based radio module
footprint deRFsamR21E-23S00
pins: 1 GND (power), 2 DNC (io) "Do Not Connect", 3 GND (power), 4 GND (power), 5 PA14/TXD (io), 6 PA15/RXD (io), 7 PA16/SPI_MISO (io), 8 PA17/SPI_CLK (io), 9 PA18/SPI_SS (io), 10 PA19/SPI_MOSI (io), 11 PA24/USBDM (io), 12 PA25/USBDP (io), 13 VCC (power), 14 VCC (power), 15 GND (power), 16 GND (power), 17 PA27 (io), 18 PA28 (io), 19 PA30/SWCLK (io), 20 PA31/SWDIO (io), 21 ~{RESET} (in), 22 GND (power), 23 PA07/AIN3 (io), 24 PA06/AIN2 (io), 25 PA08/SDA (io), 26 PA09/SCL (io), 27 GND (power)

## deRFsamR21E-23S20
designator IC?
IEEE802.15.4 2.4GHz Cortex-M0 based radio module
footprint deRFsamR21E-23S20
pins: 1 GND (power), 2 DNC (io) "Do Not Connect", 3 GND (power), 4 GND (power), 5 PA14/TXD (io), 6 PA15/RXD (io), 7 PA16/SPI_MISO (io), 8 PA17/SPI_CLK (io), 9 PA18/SPI_SS (io), 10 PA19/SPI_MOSI (io), 11 PA24/USBDM (io), 12 PA25/USBDP (io), 13 VCC (power), 14 VCC (power), 15 GND (power), 16 GND (power), 17 PA27 (io), 18 PA28 (io), 19 PA30/SWCLK (io), 20 PA31/SWDIO (io), 21 ~{RESET} (in), 22 GND (power), 23 PA07/AIN3 (io), 24 PA06/AIN2 (io), 25 PA08/SDA (io), 26 PA09/SCL (io), 27 GND (power)

## deRFsamR21E-23S20_RFPAD
designator IC?, comment deRFsamR21E-23S20
IEEE802.15.4 2.4GHz Cortex-M0 based radio module
footprint deRFsamR21E-23S20
pins: 1 GND (power), 2 RFOUT (io) "Do Not Connect", 3 GND (power), 4 GND (power), 5 PA14/TXD (io), 6 PA15/RXD (io), 7 PA16/SPI_MISO (io), 8 PA17/SPI_CLK (io), 9 PA18/SPI_SS (io), 10 PA19/SPI_MOSI (io), 11 PA24/USBDM (io), 12 PA25/USBDP (io), 13 VCC (power), 14 VCC (power), 15 GND (power), 16 GND (power), 17 PA27 (io), 18 PA28 (io), 19 PA30/SWCLK (io), 20 PA31/SWDIO (io), 21 ~{RESET} (in), 22 GND (power), 23 PA07/AIN3 (io), 24 PA06/AIN2 (io), 25 PA08/SDA (io), 26 PA09/SCL (io), 27 GND (power)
